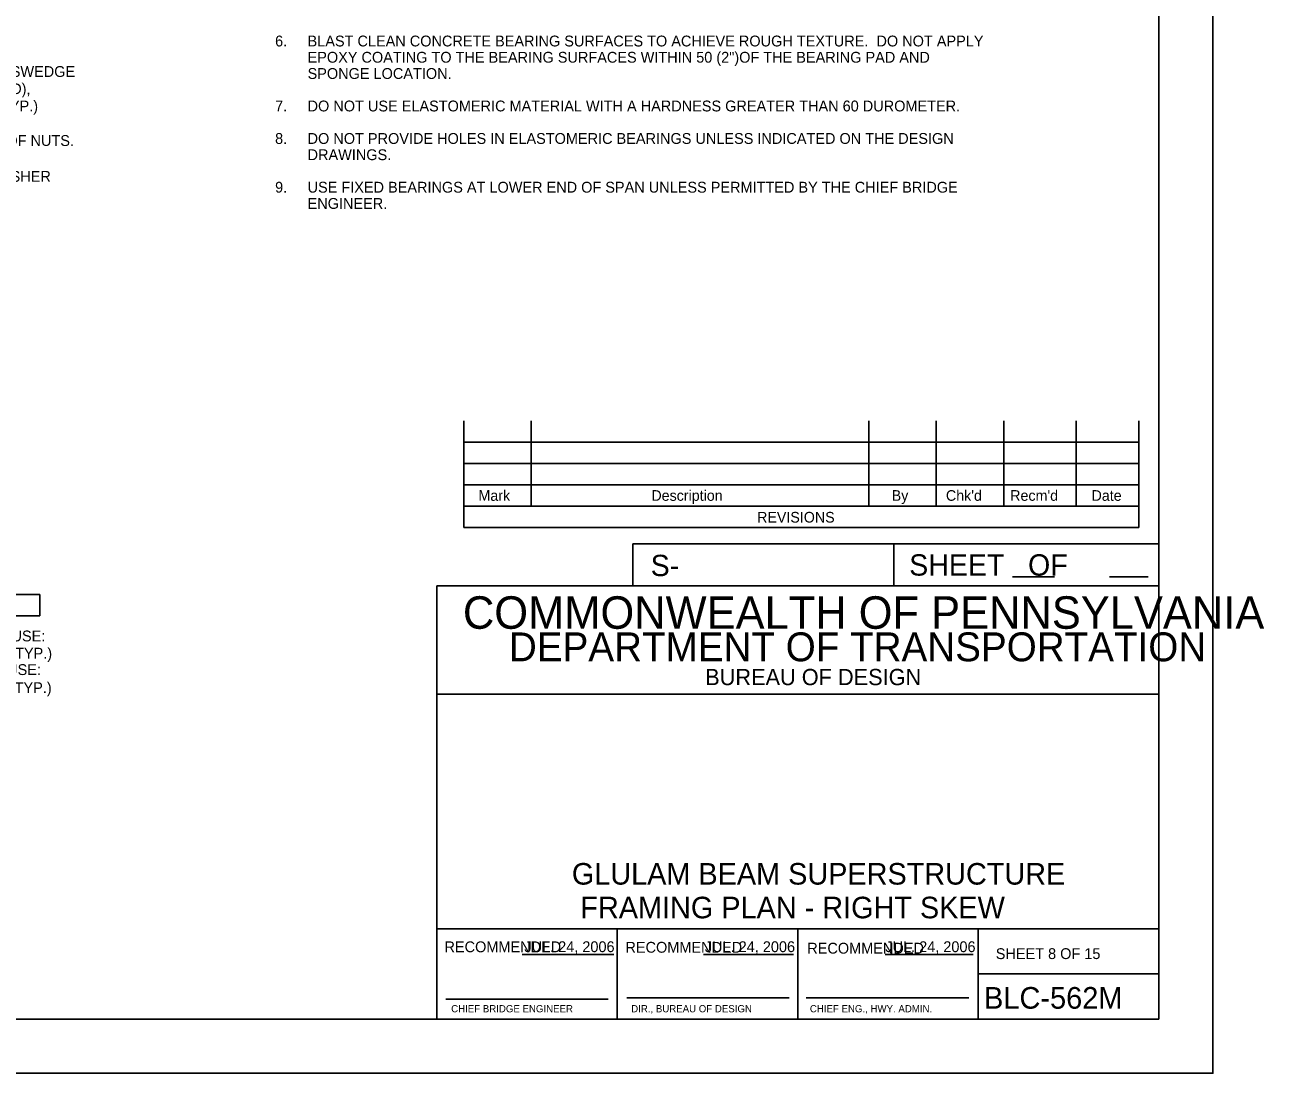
# Model space of a CAD drawing. Extents: x 638263 to 640360, y 293683 to 298655.
# Drawn here: x 638947.3 to 639290.7, y 293683.5 to 293973.9 of the extents above; entities that cross this region are included whole.
import ezdxf

# ---------------------------------------------------------------- set-up
doc = ezdxf.new("R2010")
doc.units = 0
for name, color, linetype in [('2', 7, 'Continuous'), ('4', 7, 'Continuous'), ('PLT-BNDY', 7, 'Continuous')]:
    doc.layers.add(name, color=color, linetype=linetype)

msp = doc.modelspace()

# ---------------------------------------------------------------- linework, layer by layer
at = {"layer": '2'}
for p, q in [((639261.46, 294262.46), (639261.46, 293698.46)), ((639068.92, 293864.15), (639068.92, 293834.62)), ((639087.62, 293864.15), (639087.62, 293840.53)), ((639181.13, 293864.15), (639181.13, 293840.53)), ((639199.83, 293864.15), (639199.83, 293840.53)), ((639218.53, 293864.15), (639218.53, 293840.53)), ((639238.59, 293864.15), (639238.59, 293840.53)), ((639255.94, 293864.15), (639255.94, 293834.62)), ((639255.94, 293858.24), (639068.92, 293858.24)), ((639255.94, 293852.34), (639068.92, 293852.34)), ((639255.94, 293846.43), (639068.92, 293846.43)), ((639255.94, 293840.53), (639068.92, 293840.53)), ((639255.94, 293834.62), (639068.92, 293834.62)), ((639261.46, 293830.11), (639115.78, 293830.11)), ((639115.78, 293830.11), (639115.78, 293818.46)), ((639188.09, 293830.11), (639188.09, 293818.46)), ((639220.95, 293821), (639232.6, 293821)), ((639247.83, 293821), (639258.56, 293821)), ((639261.46, 293818.46), (639061.46, 293818.46)), ((639061.46, 293818.46), (639061.46, 293698.46)), ((639261.46, 293698.46), (639261.46, 293818.46)), ((639261.46, 293788.46), (639061.46, 293788.46)), ((639261.46, 293723.46), (639061.46, 293723.46)), ((639111.46, 293698.46), (639111.46, 293723.46)), ((639161.46, 293723.46), (639161.46, 293698.46)), ((639211.46, 293723.46), (639211.46, 293698.46)), ((639085.11, 293716.35), (639110.49, 293716.35)), ((639135.38, 293716.35), (639160.27, 293716.35)), ((639185.65, 293716.35), (639210.06, 293716.35)), ((639211.46, 293710.96), (639261.46, 293710.96)), ((639063.96, 293703.96), (639108.96, 293703.96)), ((639114.08, 293704.33), (639159.08, 293704.33)), ((639163.83, 293704.33), (639208.83, 293704.33)), ((639261.46, 293698.46), (638475.46, 293698.46)), ((639061.46, 293698.46), (639261.46, 293698.46))]:
    msp.add_line(p, q, dxfattribs=at)
at = {"layer": '4'}
for p, q in [((638951.55, 293816.12), (638943.99, 293816.12)), ((638951.55, 293816.12), (638951.55, 293810.21)), ((638951.55, 293810.21), (638909.03, 293810.21))]:
    msp.add_line(p, q, dxfattribs=at)
at = {"layer": 'PLT-BNDY'}
msp.add_lwpolyline([(638435.46, 294277.46), (639276.46, 294277.46), (639276.46, 293683.46), (638435.46, 293683.46)], close=True, dxfattribs=at)

# ---------------------------------------------------------------- texts
at = {"layer": '2'}
for s, height, p in [('Mark', 2.952, (639073.02, 293842.03)), ('Description', 2.9523, (639120.92, 293842.03)), ('By', 2.952, (639187.49, 293842.03)), ("Chk'd", 2.952, (639202.52, 293842.03)), ("Recm'd", 2.953, (639220.33, 293842.03)), ('Date', 2.952, (639242.86, 293842.03)), ('REVISIONS', 2.952, (639150.2, 293836.01)), ('S-', 5.905, (639120.73, 293821.17)), ('COMMONWEALTH OF PENNSYLVANIA', 9, (639068.71, 293806.58)), ('DEPARTMENT OF TRANSPORTATION', 8.0002, (639081.46, 293797.58)), ('BUREAU OF DESIGN', 4.5, (639135.83, 293790.96)), ('FRAMING PLAN - RIGHT SKEW', 5.9728, (639101.25, 293726.37)), ('RECOMMENDED', 3, (639063.61, 293716.97)), ('JUL. 24, 2006', 3, (639085.74, 293717)), ('RECOMMENDED', 3, (639113.74, 293716.84)), ('JUL. 24, 2006', 3, (639135.74, 293717)), ('RECOMMENDED', 3, (639164.11, 293716.59)), ('JUL. 24, 2006', 3, (639185.74, 293717)), ('SHEET 8 OF 15', 3, (639216.33, 293715.08)), ('BLC-562M', 6, (639213.08, 293701.33)), ('CHIEF BRIDGE ENGINEER', 2.0002, (639065.46, 293700.33)), ('DIR., BUREAU OF DESIGN', 2.0002, (639115.33, 293700.33)), ('CHIEF ENG., HWY. ADMIN.', 2.0002, (639164.83, 293700.33))]:
    msp.add_text(s, height=height, dxfattribs=at).set_placement(p)
msp.add_text('SHEET   OF', height=5.907, rotation=360, dxfattribs=at).set_placement((639192.35, 293821.31))
at = {"layer": '4'}
for s, height, p in [('6.', 3, (639016.68, 293967.91)), ('BLAST CLEAN CONCRETE BEARING SURFACES TO ACHIEVE ROUGH TEXTURE.  DO NOT APPLY', 3, (639025.68, 293967.91)), ('EPOXY COATING TO THE BEARING SURFACES WITHIN 50 (2")OF THE BEARING PAD AND', 3, (639025.68, 293963.41)), ('FOR CONC. ABUT. USE: 38.1 (1 1/2")  STEEL SWEDGE', 3, (638858.43, 293959.46)), ('SPONGE LOCATION.', 3, (639025.68, 293958.91)), ('ANCHOR BOLT (UNLESS OTHERWISE NOTED), ', 3, (638858.43, 293954.68)), ('HEX NUT, JAM NUT & 10 (3/8") P WASHER (TYP.)', 3, (638858.43, 293949.9)), ('7.', 3, (639016.68, 293949.91)), ('DO NOT USE ELASTOMERIC MATERIAL WITH A HARDNESS GREATER THAN 60 DUROMETER.', 3, (639025.68, 293949.91)), ('8.', 3, (639016.68, 293940.91)), ('DO NOT PROVIDE HOLES IN ELASTOMERIC BEARINGS UNLESS INDICATED ON THE DESIGN', 3, (639025.68, 293940.91)), ('TURN AND PEEN BOLT THREADS AT FACE OF NUTS.', 3, (638858.43, 293940.34)), ('DRAWINGS.', 3, (639025.68, 293936.41)), ('305 (1\'-0") LONG LAG SCREW, 10 (3/8") P WASHER', 3, (638858.43, 293930.41)), ('9.', 3, (639016.68, 293927.41)), ('USE FIXED BEARINGS AT LOWER END OF SPAN UNLESS PERMITTED BY THE CHIEF BRIDGE ', 3, (639025.68, 293927.41)), ('ENGINEER.', 3, (639025.68, 293922.91)), ('FOR CONC. ABUT. USE:', 3, (638907.11, 293803.09)), ('54.0 (2 1/8")  HOLE (TYP.)', 3, (638907.11, 293798.31)), ('FOR TIMBER SILL USE:', 3, (638907.23, 293793.77)), ('35.0 (1 3/8")  HOLE (TYP.)', 3, (638906.99, 293788.75)), ('GLULAM BEAM SUPERSTRUCTURE', 5.9728, (639098.89, 293735.71))]:
    msp.add_text(s, height=height, dxfattribs=at).set_placement(p)

doc.saveas('drawing.dxf')
